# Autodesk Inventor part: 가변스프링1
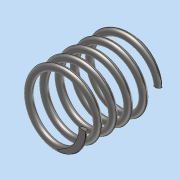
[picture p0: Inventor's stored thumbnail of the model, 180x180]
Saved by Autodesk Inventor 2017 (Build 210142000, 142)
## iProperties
Part Number: 가변스프링1
Material: 스테인레스 스틸
Document SubType Name: Modeling
Designer: MRC
Density: 8 g/cm^3
Appearance: 반연마
Mass: 6.97832 g
Surface Area: 17.713 cm^2
Volume: 0.872289 cm^3
Author: MRC
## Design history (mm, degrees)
sketch "스케치1"
  geometry: L1 (0, 0)-(0, 22.5); L2 (0, 22.5)-(9, 22.5); L3 (0, 0)-(9, 0); C1 r 1 at (9, 0)
  constraints: 6 end point, 2 horizontal, 1 centre point, 1 coincident, 1 vertical
  dimensions: "d0" = 22.5 distance of L1.start L1.end (derived); "d1" = 9 distance of L1.end L2.end; "d2" = 9 distance of L1.start L3.end; "d3" = 2 diameter of C1
feature "코일1" sketch "스케치1" pitch "d4" = 10; turns "d6" = 5; dims "d5" = 22.5 (= d0), "d7" = 0, angle "d8" = 90 deg, angle "d9" = 90 deg, "d10" = 0, "d11" = 0
sketch "스케치2"
  geometry: L1 (22.5, 21.748)-(0, 21.748); L2 (0, 21.748)-(0, -21.748); L3 (0, -21.748)-(22.5, -21.748); L4 (22.5, -21.748)-(22.5, 21.748); 2 further points
  constraints: 8 end point, 2 midpoint, 2 parallel, 1 coincident, 1 horizontal, 1 perpendicular
  dimensions: "d12" = 22.5 distance of L2.end L3.end (= d0); "d13" = 43.49633 distance of L3.end L1.start
extrude "돌출1" sketch "스케치2" stored distance "d14" = 0; taper "d15" = 0 deg
node "솔리드1"
